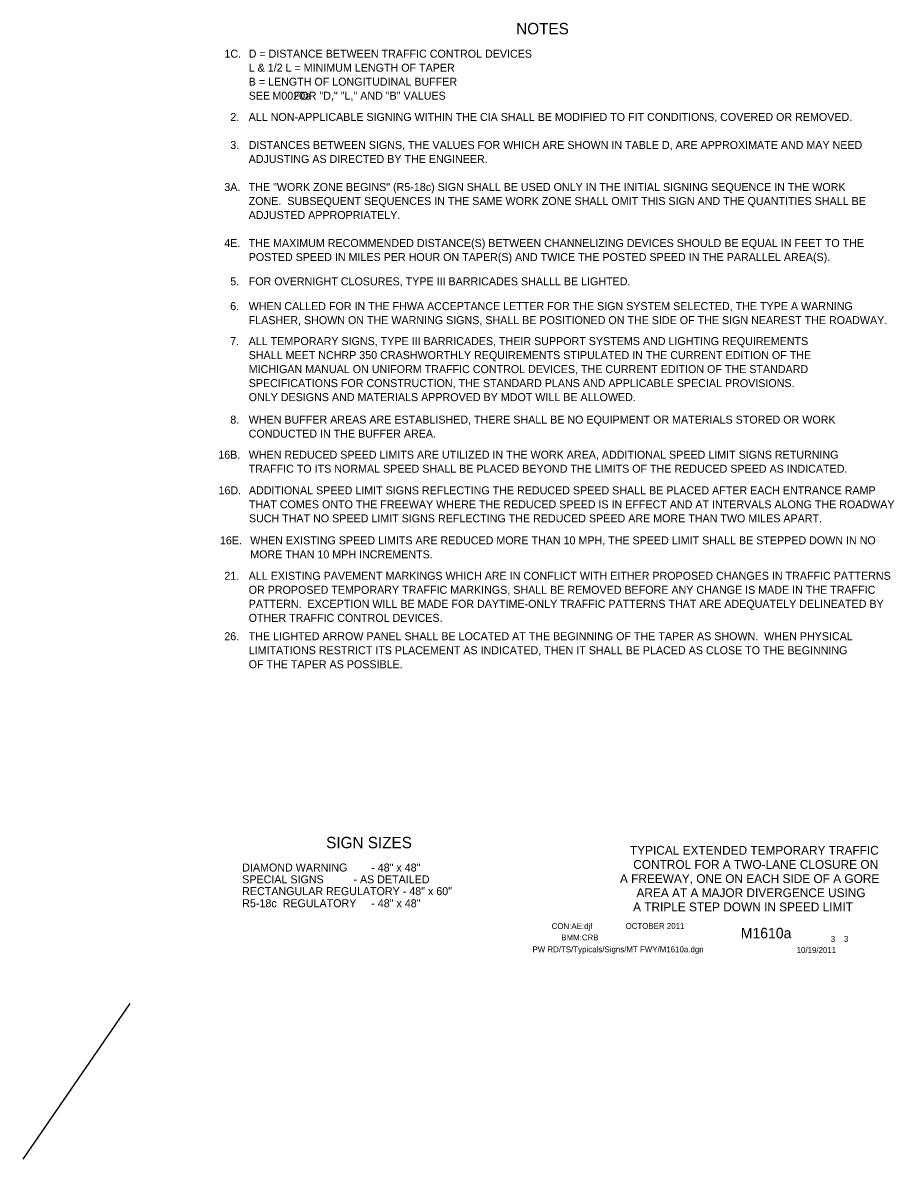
# Model space of a CAD drawing. Extents: x 16554 to 19508, y 5694 to 7079.
# Drawn here: x 18593 to 19508, y 5717 to 6909 of the extents above; entities that cross this region are included whole.
import ezdxf

# ---------------------------------------------------------------- set-up
doc = ezdxf.new("R2010")
doc.units = 0
for name, color, linetype in [('BORDER', 7, 'Continuous'), ('BORDER_SIGNAL_WO', 7, 'Continuous'), ('TYPICAL_TEXT_DIMEN_PR', 7, 'Continuous')]:
    doc.layers.add(name, color=color, linetype=linetype)

msp = doc.modelspace()

# ---------------------------------------------------------------- linework, layer by layer
at = {"layer": 'TYPICAL_TEXT_DIMEN_PR'}
msp.add_line((18705.8, 5880), (18593.5, 5716.6), dxfattribs=at)

# ---------------------------------------------------------------- texts
at = {"layer": 'BORDER'}
for s, p in [('TYPICAL EXTENDED TEMPORARY TRAFFIC', (19230.9, 6036.1)), ('CONTROL FOR A TWO-LANE CLOSURE ON', (19234.4, 6021.3)), ('A FREEWAY, ONE ON EACH SIDE OF A GORE', (19220.4, 6006.4)), ('AREA AT A MAJOR DIVERGENCE USING', (19237.8, 5991.6)), ('A TRIPLE STEP DOWN IN SPEED LIMIT', (19234.2, 5976.7))]:
    msp.add_text(s, height=9.3, dxfattribs=at).set_placement(p)
at = {"layer": 'BORDER_SIGNAL_WO'}
for s, height, p in [('CON:AE:djf  ', 6.2, (19148.7, 5958.1)), ('    OCTOBER 2011    ', 6.2, (19217.1, 5958.3)), ('BMM:CRB   ', 6.2, (19158.8, 5946.2)), ('    M1610a   ', 11, (19330.9, 5948.4)), ('PW RD/TS/Typicals/Signs/MT FWY/M1610a.dgn      ', 6.2, (19128.6, 5933.7)), ('10/19/2011    ', 6.2, (19405.9, 5933.1)), (' 3    3 ', 6.2, (19439.4, 5944.7))]:
    msp.add_text(s, height=height, dxfattribs=at).set_placement(p)
at = {"layer": 'TYPICAL_TEXT_DIMEN_PR'}
for s, height, p in [('NOTES', 12, (19111.5, 6897)), ('1C.', 8.4, (18805.2, 6872.5)), ('D = DISTANCE BETWEEN TRAFFIC CONTROL DEVICES', 8.4, (18830.7, 6872.5)), ('L & 1/2 L = MINIMUM LENGTH OF TAPER', 8.4, (18830.7, 6857.8)), ('B = LENGTH OF LONGITUDINAL BUFFER', 8.4, (18830.7, 6843.1)), ('SEE        FOR "D," "L," AND "B" VALUES', 8.4, (18830.7, 6828.4)), ('M0020a', 8.4, (18855.6, 6828.4)), ('2.', 8.4, (18811.4, 6806.1)), ('ALL NON-APPLICABLE SIGNING WITHIN THE CIA SHALL BE MODIFIED TO FIT CONDITIONS, COVERED OR REMOVED.', 8.4, (18830.7, 6806.1)), ('3.', 8.4, (18811.4, 6776.7)), ('DISTANCES BETWEEN SIGNS, THE VALUES FOR WHICH ARE SHOWN IN TABLE D, ARE APPROXIMATE AND MAY NEED', 8.4, (18830.7, 6776.7)), ('ADJUSTING AS DIRECTED BY THE ENGINEER.', 8.4, (18830.7, 6762)), ('3A.', 8.4, (18805.1, 6732.6)), ('THE "WORK ZONE BEGINS" (R5-18c) SIGN SHALL BE USED ONLY IN THE INITIAL SIGNING SEQUENCE IN THE WORK', 8.4, (18830.7, 6732.6)), ('ZONE.  SUBSEQUENT SEQUENCES IN THE SAME WORK ZONE SHALL OMIT THIS SIGN AND THE QUANTITIES SHALL BE', 8.4, (18830.7, 6717.9)), ('ADJUSTED APPROPRIATELY.', 8.4, (18830.7, 6703.2)), ('4E.', 8.4, (18805.1, 6673.8)), ('THE MAXIMUM RECOMMENDED DISTANCE(S) BETWEEN CHANNELIZING DEVICES SHOULD BE EQUAL IN FEET TO THE', 8.4, (18830.7, 6673.8)), ('POSTED SPEED IN MILES PER HOUR ON TAPER(S) AND TWICE THE POSTED SPEED IN THE PARALLEL AREA(S).', 8.4, (18830.7, 6659.1)), ('5.', 8.4, (18811.4, 6633.6)), ('FOR OVERNIGHT CLOSURES, TYPE III BARRICADES SHALLL BE LIGHTED. ', 8.4, (18830.7, 6633.6)), ('6.', 8.4, (18811.3, 6607.6)), ('WHEN CALLED FOR IN THE FHWA ACCEPTANCE LETTER FOR THE SIGN SYSTEM SELECTED, THE TYPE A WARNING ', 8.4, (18830.7, 6607.6)), ('FLASHER, SHOWN ON THE WARNING SIGNS, SHALL BE POSITIONED ON THE SIDE OF THE SIGN NEAREST THE ROADWAY.', 8.4, (18830.7, 6592.9)), ('7.', 8.4, (18811.3, 6570.9)), ('ALL TEMPORARY SIGNS, TYPE III BARRICADES, THEIR SUPPORT SYSTEMS AND LIGHTING REQUIREMENTS', 8.4, (18830.7, 6570.9)), ('SHALL MEET NCHRP 350 CRASHWORTHLY REQUIREMENTS STIPULATED IN THE CURRENT EDITION OF THE', 8.4, (18830.7, 6556.2)), ('MICHIGAN MANUAL ON UNIFORM TRAFFIC CONTROL DEVICES, THE CURRENT EDITION OF THE STANDARD', 8.4, (18830.7, 6541.5)), ('SPECIFICATIONS FOR CONSTRUCTION, THE STANDARD PLANS AND APPLICABLE SPECIAL PROVISIONS.', 8.4, (18830.7, 6526.8)), ('ONLY DESIGNS AND MATERIALS APPROVED BY MDOT WILL BE ALLOWED.', 8.4, (18830.7, 6512.1)), ('8.', 8.4, (18811.4, 6488.5)), ('WHEN BUFFER AREAS ARE ESTABLISHED, THERE SHALL BE NO EQUIPMENT OR MATERIALS STORED OR WORK     ', 8.4, (18830.7, 6488.5)), ('CONDUCTED IN THE BUFFER AREA.', 8.4, (18830.7, 6473.8)), ('16B.', 8.4, (18798.8, 6451.7)), ('WHEN REDUCED SPEED LIMITS ARE UTILIZED IN THE WORK AREA, ADDITIONAL SPEED LIMIT SIGNS RETURNING', 8.4, (18830.7, 6451.7)), ('TRAFFIC TO ITS NORMAL SPEED SHALL BE PLACED BEYOND THE LIMITS OF THE REDUCED SPEED AS INDICATED.', 8.4, (18830.7, 6437)), ('16D.', 8.4, (18799, 6414.3)), ('ADDITIONAL SPEED LIMIT SIGNS REFLECTING THE REDUCED SPEED SHALL BE PLACED AFTER EACH ENTRANCE RAMP', 8.4, (18830.9, 6414.3)), ('THAT COMES ONTO THE FREEWAY WHERE THE REDUCED SPEED IS IN EFFECT AND AT INTERVALS ALONG THE ROADWAY', 8.4, (18830.9, 6399.6)), ('SUCH THAT NO SPEED LIMIT SIGNS REFLECTING THE REDUCED SPEED ARE MORE THAN TWO MILES APART.', 8.4, (18830.9, 6384.9)), ('16E.', 8.4, (18800.5, 6361.8)), ('WHEN EXISTING SPEED LIMITS ARE REDUCED MORE THAN 10 MPH, THE SPEED LIMIT SHALL BE STEPPED DOWN IN NO', 8.4, (18832.3, 6361.8)), ('MORE THAN 10 MPH INCREMENTS.', 8.4, (18832.3, 6347.1)), ('21.', 8.4, (18805.1, 6324.6)), ('ALL EXISTING PAVEMENT MARKINGS WHICH ARE IN CONFLICT WITH EITHER PROPOSED CHANGES IN TRAFFIC PATTERNS', 8.4, (18830.7, 6324.6)), ('OR PROPOSED TEMPORARY TRAFFIC MARKINGS, SHALL BE REMOVED BEFORE ANY CHANGE IS MADE IN THE TRAFFIC', 8.4, (18830.7, 6309.9)), ('PATTERN.  EXCEPTION WILL BE MADE FOR DAYTIME-ONLY TRAFFIC PATTERNS THAT ARE ADEQUATELY DELINEATED BY', 8.4, (18830.7, 6295.2)), ('OTHER TRAFFIC CONTROL DEVICES.', 8.4, (18830.7, 6280.5)), ('26.', 8.4, (18805.1, 6261.2)), ('THE LIGHTED ARROW PANEL SHALL BE LOCATED AT THE BEGINNING OF THE TAPER AS SHOWN.  WHEN PHYSICAL', 8.4, (18830.7, 6261.2)), ('LIMITATIONS RESTRICT ITS PLACEMENT AS INDICATED, THEN IT SHALL BE PLACED AS CLOSE TO THE BEGINNING', 8.4, (18830.7, 6246.5)), ('OF THE TAPER AS POSSIBLE.', 8.4, (18830.7, 6231.8)), ('SIGN SIZES', 12, (18912, 6042.9)), ('DIAMOND WARNING        - 48" x 48"', 8.4, (18823.9, 6018.5)), ('SPECIAL SIGNS          - AS DETAILED', 8.4, (18823.9, 6006.1)), ('RECTANGULAR REGULATORY - 48" x 60"', 8.4, (18823.9, 5993.7)), ('R5-18c  REGULATORY     - 48" x 48"', 8.4, (18823.9, 5981))]:
    msp.add_text(s, height=height, dxfattribs=at).set_placement(p)

doc.saveas('drawing.dxf')
